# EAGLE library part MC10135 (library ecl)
Dual J-K Master Slave Flip-Flop
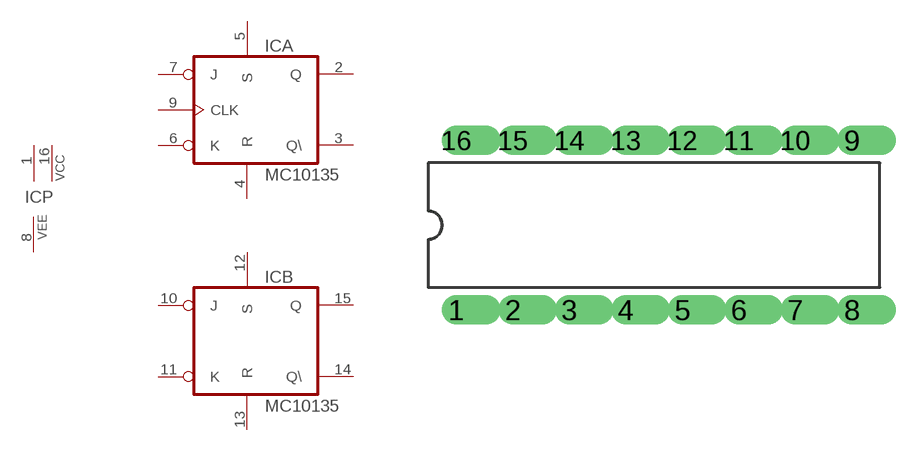
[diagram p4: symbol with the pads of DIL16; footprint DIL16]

Designator prefix IC; gates P=2VCC1VEE A=MC10135 A1=CLK B=MC10135

## MC10135  [DIL16]
1  P:VCC  pwr
2  A:Q  out
3  A:Q\  out
4  A:R  in
5  A:S  in
6  A:K  in
7  A:J  in
8  P:VEE  pwr
9  A1:CLK  in
10  B:J  in
11  B:K  in
12  B:S  in
13  B:R  in
14  B:Q\  out
15  B:Q  out
16  P:VCC  pwr

## Footprint DIL16 (pad centres in mm)
drill 0.813 offset: 1 -8.89,-3.81; 2 -6.35,-3.81; 3 -3.81,-3.81; 4 -1.27,-3.81; 5 1.27,-3.81; 6 3.81,-3.81; 7 6.35,-3.81; 8 8.89,-3.81; 9 8.89,3.81; 10 6.35,3.81; 11 3.81,3.81; 12 1.27,3.81; 13 -1.27,3.81; 14 -3.81,3.81; 15 -6.35,3.81; 16 -8.89,3.81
